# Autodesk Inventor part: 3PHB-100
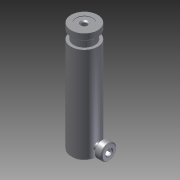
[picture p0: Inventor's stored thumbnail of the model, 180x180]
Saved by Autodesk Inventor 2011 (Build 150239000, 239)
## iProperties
Created: 2011-07
Part Number: 3PHB-100
Document SubType Name: Modeling
Designer: vadybininkas6
Density: 1 g/cm^3
Author: vadybininkas6
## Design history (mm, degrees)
feature "Base1"
body "Solid1"
